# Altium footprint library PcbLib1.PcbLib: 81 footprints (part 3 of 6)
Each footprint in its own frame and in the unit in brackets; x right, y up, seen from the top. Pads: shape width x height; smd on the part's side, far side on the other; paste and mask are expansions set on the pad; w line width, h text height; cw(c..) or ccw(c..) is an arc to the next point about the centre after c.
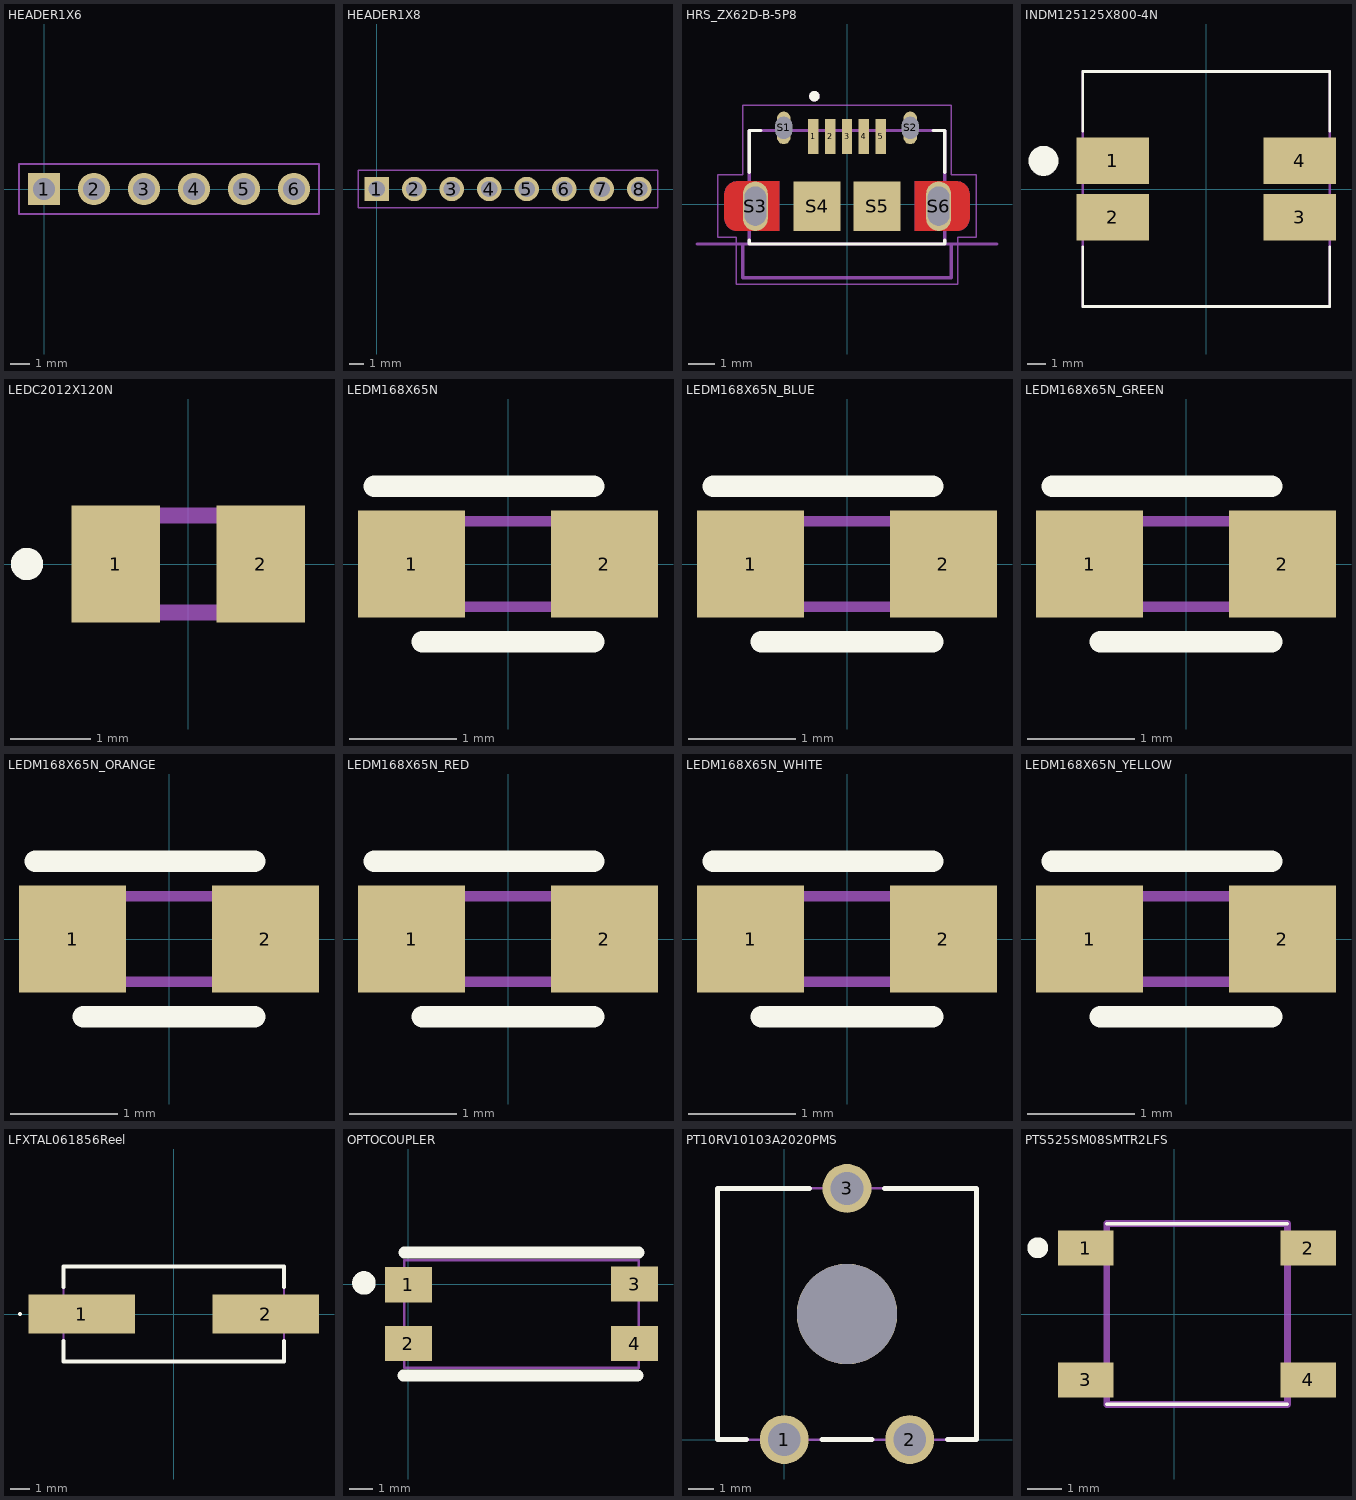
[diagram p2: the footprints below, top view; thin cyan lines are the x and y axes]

## HEADER1X6 [mm]
pads (6):
  rect 1.65x1.65 hole 1.1: 1(0,0)
  round 1.65 hole 1.1: 2(2.54,0) 3(5.08,0) 4(7.62,0) 5(10.16,0) 6(12.7,0)
Mechanical 13:
  lines w0.1: -1.27,-1.27 -1.27,1.27 13.97,1.27 13.97,-1.27 -1.27,-1.27
3D body "0901471106.stp": height 8.7, standoff -3.1, extent -1.195,-1.22 13.895,1.22

## HEADER1X8 [mm]
pads (8):
  rect 1.65x1.65 hole 1.1: 1(0,0)
  round 1.65 hole 1.1: 2(2.54,0) 3(5.08,0) 4(7.62,0) 5(10.16,0) 6(12.7,0) 7(15.24,0) 8(17.78,0)
Mechanical 13:
  lines w0.1: -1.27,-1.27 19.05,-1.27 19.05,1.27 -1.27,1.27 -1.27,-1.27
3D body "m20-9990246_asm.stp": height 8.7, standoff -2.98, extent 13.97,-1.27 19.05,1.27
3D body "m20-9990246_asm.stp": height 8.7, standoff -2.98, extent 8.89,-1.27 13.97,1.27
3D body "m20-9990246_asm.stp": height 8.7, standoff -2.98, extent 3.81,-1.27 8.89,1.27
3D body "m20-9990246_asm.stp": height 8.7, standoff -2.98, extent -1.27,-1.27 3.81,1.27

## HRS_ZX62D-B-5P8 [mm]
pads (11):
  rect 0.4x1.35 smd mask+0.1: 1(-1.3,2.6) 2(-0.65,2.6) 3(0,2.6) 4(0.65,2.6) 5(1.3,2.6)
  oval 0.525x1.25 hole 0.65 slot 0.85 at 90 deg mask+0.1: S1(-2.425,2.925) S2(2.425,2.925)
  oval 0.95x1.9 hole 0.825 slot 1.5 at 90 deg mask+0.1: S3(-3.512,-0.075) S6(3.512,-0.075)
  rect 1.8x1.9 smd mask+0.1: S4(-1.15,-0.075) S5(1.15,-0.075)
Top Layer:
  region: -2.6,-0.075 -3.1,-0.075 -3.1,0.375 -3.1,0.391 -3.102,0.406 -3.104,0.422 -3.107,0.437 -3.11,0.453 -3.115,0.468 -3.12,0.483 -3.126,0.497 -3.133,0.511 -3.14,0.525 -3.148,0.538 -3.157,0.551 -3.167,0.564 -3.177,0.576 -3.188,0.587 -3.199,0.598 -3.211,0.608 -3.224,0.618 -3.237,0.627 -3.25,0.635 -3.264,0.642 -3.278,0.649 -3.292,0.655 -3.307,0.66 -3.322,0.665 -3.338,0.668 -3.353,0.671 -3.369,0.673 -3.384,0.675 -3.641,0.675 -3.656,0.673 -3.672,0.671 -3.687,0.668 -3.703,0.665 -3.718,0.66 -3.733,0.655 -3.747,0.649 -3.761,0.642 -3.775,0.635 -3.788,0.627 -3.801,0.618 -3.814,0.608 -3.826,0.598 -3.837,0.587 -3.848,0.576 -3.858,0.564 -3.868,0.551 -3.877,0.538 -3.885,0.525 -3.892,0.511 -3.899,0.497 -3.905,0.483 -3.91,0.468 -3.915,0.453 -3.918,0.437 -3.921,0.422 -3.923,0.406 -3.925,0.391 -3.925,0.375 -3.925,-0.075 -4.7,-0.075 -4.7,0.375 -4.699,0.401 -4.697,0.427 -4.694,0.453 -4.689,0.479 -4.683,0.504 -4.676,0.53 -4.667,0.554 -4.657,0.578 -4.646,0.602 -4.633,0.625 -4.619,0.647 -4.605,0.669 -4.589,0.69 -4.572,0.71 -4.554,0.729 -4.535,0.747 -4.515,0.764 -4.494,0.78 -4.472,0.794 -4.45,0.808 -4.427,0.821 -4.403,0.832 -4.379,0.842 -4.355,0.851 -4.329,0.858 -4.304,0.864 -4.278,0.869 -4.252,0.872 -4.226,0.874 -4.2,0.875 -2.6,0.875
  region: 4.7,-0.525 4.699,-0.551 4.697,-0.577 4.694,-0.603 4.689,-0.629 4.683,-0.654 4.676,-0.68 4.667,-0.704 4.657,-0.728 4.646,-0.752 4.633,-0.775 4.619,-0.797 4.605,-0.819 4.589,-0.84 4.572,-0.86 4.554,-0.879 4.535,-0.897 4.515,-0.914 4.494,-0.93 4.472,-0.944 4.45,-0.958 4.427,-0.971 4.403,-0.982 4.379,-0.992 4.355,-1.001 4.329,-1.008 4.304,-1.014 4.278,-1.019 4.252,-1.022 4.226,-1.024 4.2,-1.025 2.6,-1.025 2.6,-0.075 3.1,-0.075 3.1,-0.525 3.1,-0.541 3.102,-0.556 3.104,-0.572 3.107,-0.587 3.11,-0.603 3.115,-0.618 3.12,-0.633 3.126,-0.647 3.133,-0.661 3.14,-0.675 3.148,-0.688 3.157,-0.701 3.167,-0.714 3.177,-0.726 3.188,-0.737 3.199,-0.748 3.211,-0.758 3.224,-0.768 3.237,-0.777 3.25,-0.785 3.264,-0.792 3.278,-0.799 3.292,-0.805 3.307,-0.81 3.322,-0.815 3.338,-0.818 3.353,-0.821 3.369,-0.823 3.384,-0.825 3.641,-0.825 3.656,-0.823 3.672,-0.821 3.687,-0.818 3.703,-0.815 3.718,-0.81 3.733,-0.805 3.747,-0.799 3.761,-0.792 3.775,-0.785 3.788,-0.777 3.801,-0.768 3.814,-0.758 3.826,-0.748 3.837,-0.737 3.848,-0.726 3.858,-0.714 3.868,-0.701 3.877,-0.688 3.885,-0.675 3.892,-0.661 3.899,-0.647 3.905,-0.633 3.91,-0.618 3.915,-0.603 3.918,-0.587 3.921,-0.572 3.923,-0.556 3.925,-0.541 3.925,-0.525 3.925,-0.075 4.7,-0.075
  region: -2.6,-1.025 -4.2,-1.025 -4.226,-1.024 -4.252,-1.022 -4.278,-1.019 -4.304,-1.014 -4.329,-1.008 -4.355,-1.001 -4.379,-0.992 -4.403,-0.982 -4.427,-0.971 -4.45,-0.958 -4.472,-0.944 -4.494,-0.93 -4.515,-0.914 -4.535,-0.897 -4.554,-0.879 -4.572,-0.86 -4.589,-0.84 -4.605,-0.819 -4.619,-0.797 -4.633,-0.775 -4.646,-0.752 -4.657,-0.728 -4.667,-0.704 -4.676,-0.68 -4.683,-0.654 -4.689,-0.629 -4.694,-0.603 -4.697,-0.577 -4.699,-0.551 -4.7,-0.525 -4.7,-0.075 -3.925,-0.075 -3.925,-0.55 -3.925,-0.564 -3.923,-0.579 -3.922,-0.593 -3.919,-0.607 -3.916,-0.621 -3.912,-0.635 -3.907,-0.649 -3.901,-0.662 -3.895,-0.675 -3.888,-0.688 -3.881,-0.7 -3.872,-0.712 -3.864,-0.723 -3.854,-0.734 -3.844,-0.744 -3.834,-0.754 -3.823,-0.764 -3.812,-0.772 -3.8,-0.781 -3.787,-0.788 -3.775,-0.795 -3.762,-0.801 -3.749,-0.807 -3.735,-0.812 -3.721,-0.816 -3.707,-0.819 -3.693,-0.822 -3.679,-0.823 -3.664,-0.825 -3.384,-0.825 -3.369,-0.823 -3.353,-0.821 -3.338,-0.818 -3.322,-0.815 -3.307,-0.81 -3.292,-0.805 -3.278,-0.799 -3.264,-0.792 -3.25,-0.785 -3.237,-0.777 -3.224,-0.768 -3.211,-0.758 -3.199,-0.748 -3.188,-0.737 -3.177,-0.726 -3.167,-0.714 -3.157,-0.701 -3.148,-0.688 -3.14,-0.675 -3.133,-0.661 -3.126,-0.647 -3.12,-0.633 -3.115,-0.618 -3.11,-0.603 -3.107,-0.587 -3.104,-0.572 -3.102,-0.556 -3.1,-0.541 -3.1,-0.525 -3.1,-0.075 -2.6,-0.075
  region: 4.226,0.874 4.252,0.872 4.278,0.869 4.304,0.864 4.329,0.858 4.355,0.851 4.379,0.842 4.403,0.832 4.427,0.821 4.45,0.808 4.472,0.794 4.494,0.78 4.515,0.764 4.535,0.747 4.554,0.729 4.572,0.71 4.589,0.69 4.605,0.669 4.619,0.647 4.633,0.625 4.646,0.602 4.657,0.578 4.667,0.554 4.676,0.53 4.683,0.504 4.689,0.479 4.694,0.453 4.697,0.427 4.699,0.401 4.7,0.375 4.7,-0.075 3.925,-0.075 3.925,0.4 3.925,0.414 3.923,0.429 3.922,0.443 3.919,0.457 3.916,0.471 3.912,0.485 3.907,0.499 3.901,0.512 3.895,0.525 3.888,0.538 3.881,0.55 3.872,0.562 3.864,0.573 3.854,0.584 3.844,0.594 3.834,0.604 3.823,0.614 3.812,0.622 3.8,0.631 3.787,0.638 3.775,0.645 3.762,0.651 3.749,0.657 3.735,0.662 3.721,0.666 3.707,0.669 3.693,0.672 3.679,0.673 3.664,0.675 3.384,0.675 3.369,0.673 3.353,0.671 3.338,0.668 3.322,0.665 3.307,0.66 3.292,0.655 3.278,0.649 3.264,0.642 3.25,0.635 3.237,0.627 3.224,0.618 3.211,0.608 3.199,0.598 3.188,0.587 3.177,0.576 3.167,0.564 3.157,0.551 3.148,0.538 3.14,0.525 3.133,0.511 3.126,0.497 3.12,0.483 3.115,0.468 3.11,0.453 3.107,0.437 3.104,0.422 3.102,0.406 3.1,0.391 3.1,0.375 3.1,-0.075 2.6,-0.075 2.6,0.875 4.2,0.875
Bottom Layer:
  region: -2.6,-0.075 -3.1,-0.075 -3.1,0.375 -3.1,0.391 -3.102,0.406 -3.104,0.422 -3.107,0.437 -3.11,0.453 -3.115,0.468 -3.12,0.483 -3.126,0.497 -3.133,0.511 -3.14,0.525 -3.148,0.538 -3.157,0.551 -3.167,0.564 -3.177,0.576 -3.188,0.587 -3.199,0.598 -3.211,0.608 -3.224,0.618 -3.237,0.627 -3.25,0.635 -3.264,0.642 -3.278,0.649 -3.292,0.655 -3.307,0.66 -3.322,0.665 -3.338,0.668 -3.353,0.671 -3.369,0.673 -3.384,0.675 -3.641,0.675 -3.656,0.673 -3.672,0.671 -3.687,0.668 -3.703,0.665 -3.718,0.66 -3.733,0.655 -3.747,0.649 -3.761,0.642 -3.775,0.635 -3.788,0.627 -3.801,0.618 -3.814,0.608 -3.826,0.598 -3.837,0.587 -3.848,0.576 -3.858,0.564 -3.868,0.551 -3.877,0.538 -3.885,0.525 -3.892,0.511 -3.899,0.497 -3.905,0.483 -3.91,0.468 -3.915,0.453 -3.918,0.437 -3.921,0.422 -3.923,0.406 -3.925,0.391 -3.925,0.375 -3.925,-0.075 -4.7,-0.075 -4.7,0.375 -4.699,0.401 -4.697,0.427 -4.694,0.453 -4.689,0.479 -4.683,0.504 -4.676,0.53 -4.667,0.554 -4.657,0.578 -4.646,0.602 -4.633,0.625 -4.619,0.647 -4.605,0.669 -4.589,0.69 -4.572,0.71 -4.554,0.729 -4.535,0.747 -4.515,0.764 -4.494,0.78 -4.472,0.794 -4.45,0.808 -4.427,0.821 -4.403,0.832 -4.379,0.842 -4.355,0.851 -4.329,0.858 -4.304,0.864 -4.278,0.869 -4.252,0.872 -4.226,0.874 -4.2,0.875 -2.6,0.875
  region: 4.7,-0.525 4.699,-0.551 4.697,-0.577 4.694,-0.603 4.689,-0.629 4.683,-0.654 4.676,-0.68 4.667,-0.704 4.657,-0.728 4.646,-0.752 4.633,-0.775 4.619,-0.797 4.605,-0.819 4.589,-0.84 4.572,-0.86 4.554,-0.879 4.535,-0.897 4.515,-0.914 4.494,-0.93 4.472,-0.944 4.45,-0.958 4.427,-0.971 4.403,-0.982 4.379,-0.992 4.355,-1.001 4.329,-1.008 4.304,-1.014 4.278,-1.019 4.252,-1.022 4.226,-1.024 4.2,-1.025 2.6,-1.025 2.6,-0.075 3.1,-0.075 3.1,-0.525 3.1,-0.541 3.102,-0.556 3.104,-0.572 3.107,-0.587 3.11,-0.603 3.115,-0.618 3.12,-0.633 3.126,-0.647 3.133,-0.661 3.14,-0.675 3.148,-0.688 3.157,-0.701 3.167,-0.714 3.177,-0.726 3.188,-0.737 3.199,-0.748 3.211,-0.758 3.224,-0.768 3.237,-0.777 3.25,-0.785 3.264,-0.792 3.278,-0.799 3.292,-0.805 3.307,-0.81 3.322,-0.815 3.338,-0.818 3.353,-0.821 3.369,-0.823 3.384,-0.825 3.641,-0.825 3.656,-0.823 3.672,-0.821 3.687,-0.818 3.703,-0.815 3.718,-0.81 3.733,-0.805 3.747,-0.799 3.761,-0.792 3.775,-0.785 3.788,-0.777 3.801,-0.768 3.814,-0.758 3.826,-0.748 3.837,-0.737 3.848,-0.726 3.858,-0.714 3.868,-0.701 3.877,-0.688 3.885,-0.675 3.892,-0.661 3.899,-0.647 3.905,-0.633 3.91,-0.618 3.915,-0.603 3.918,-0.587 3.921,-0.572 3.923,-0.556 3.925,-0.541 3.925,-0.525 3.925,-0.075 4.7,-0.075
  region: -2.6,-1.025 -4.2,-1.025 -4.226,-1.024 -4.252,-1.022 -4.278,-1.019 -4.304,-1.014 -4.329,-1.008 -4.355,-1.001 -4.379,-0.992 -4.403,-0.982 -4.427,-0.971 -4.45,-0.958 -4.472,-0.944 -4.494,-0.93 -4.515,-0.914 -4.535,-0.897 -4.554,-0.879 -4.572,-0.86 -4.589,-0.84 -4.605,-0.819 -4.619,-0.797 -4.633,-0.775 -4.646,-0.752 -4.657,-0.728 -4.667,-0.704 -4.676,-0.68 -4.683,-0.654 -4.689,-0.629 -4.694,-0.603 -4.697,-0.577 -4.699,-0.551 -4.7,-0.525 -4.7,-0.075 -3.925,-0.075 -3.925,-0.55 -3.925,-0.564 -3.923,-0.579 -3.922,-0.593 -3.919,-0.607 -3.916,-0.621 -3.912,-0.635 -3.907,-0.649 -3.901,-0.662 -3.895,-0.675 -3.888,-0.688 -3.881,-0.7 -3.872,-0.712 -3.864,-0.723 -3.854,-0.734 -3.844,-0.744 -3.834,-0.754 -3.823,-0.764 -3.812,-0.772 -3.8,-0.781 -3.787,-0.788 -3.775,-0.795 -3.762,-0.801 -3.749,-0.807 -3.735,-0.812 -3.721,-0.816 -3.707,-0.819 -3.693,-0.822 -3.679,-0.823 -3.664,-0.825 -3.384,-0.825 -3.369,-0.823 -3.353,-0.821 -3.338,-0.818 -3.322,-0.815 -3.307,-0.81 -3.292,-0.805 -3.278,-0.799 -3.264,-0.792 -3.25,-0.785 -3.237,-0.777 -3.224,-0.768 -3.211,-0.758 -3.199,-0.748 -3.188,-0.737 -3.177,-0.726 -3.167,-0.714 -3.157,-0.701 -3.148,-0.688 -3.14,-0.675 -3.133,-0.661 -3.126,-0.647 -3.12,-0.633 -3.115,-0.618 -3.11,-0.603 -3.107,-0.587 -3.104,-0.572 -3.102,-0.556 -3.1,-0.541 -3.1,-0.525 -3.1,-0.075 -2.6,-0.075
  region: 4.226,0.874 4.252,0.872 4.278,0.869 4.304,0.864 4.329,0.858 4.355,0.851 4.379,0.842 4.403,0.832 4.427,0.821 4.45,0.808 4.472,0.794 4.494,0.78 4.515,0.764 4.535,0.747 4.554,0.729 4.572,0.71 4.589,0.69 4.605,0.669 4.619,0.647 4.633,0.625 4.646,0.602 4.657,0.578 4.667,0.554 4.676,0.53 4.683,0.504 4.689,0.479 4.694,0.453 4.697,0.427 4.699,0.401 4.7,0.375 4.7,-0.075 3.925,-0.075 3.925,0.4 3.925,0.414 3.923,0.429 3.922,0.443 3.919,0.457 3.916,0.471 3.912,0.485 3.907,0.499 3.901,0.512 3.895,0.525 3.888,0.538 3.881,0.55 3.872,0.562 3.864,0.573 3.854,0.584 3.844,0.594 3.834,0.604 3.823,0.614 3.812,0.622 3.8,0.631 3.787,0.638 3.775,0.645 3.762,0.651 3.749,0.657 3.735,0.662 3.721,0.666 3.707,0.669 3.693,0.672 3.679,0.673 3.664,0.675 3.384,0.675 3.369,0.673 3.353,0.671 3.338,0.668 3.322,0.665 3.307,0.66 3.292,0.655 3.278,0.649 3.264,0.642 3.25,0.635 3.237,0.627 3.224,0.618 3.211,0.608 3.199,0.598 3.188,0.587 3.177,0.576 3.167,0.564 3.157,0.551 3.148,0.538 3.14,0.525 3.133,0.511 3.126,0.497 3.12,0.483 3.115,0.468 3.11,0.453 3.107,0.437 3.104,0.422 3.102,0.406 3.1,0.391 3.1,0.375 3.1,-0.075 2.6,-0.075 2.6,0.875 4.2,0.875
Top Overlay:
  circle w0.2: c-1.25,4.14 r0.1
  lines w0.127: -3.75,-1.375 -3.75,-1.525 3.75,-1.525 3.75,-1.375 ; -3.75,1.225 -3.75,2.825 -3.3,2.825 ; 3.3,2.825 3.75,2.825 3.75,1.225
Top Paste:
  drawing of 8 lines, arcs and shapes, not listed
Bottom Paste:
  drawing of 8 lines, arcs and shapes, not listed
Top Solder:
  region: -2.5,-1.126 -4.801,-1.126 -4.801,0.975 -2.5,0.975
  region: 4.8,-1.128 2.502,-1.128 2.502,0.975 4.8,0.975
Bottom Solder:
  region: -2.5,0.875 -2.6,0.875 -2.6,-1.025 -2.5,-1.025 -2.5,-1.126 -4.801,-1.126 -4.801,0.975 -2.5,0.975
  region: 4.8,-1.128 2.502,-1.128 2.502,-1.025 2.6,-1.025 2.6,0.875 2.502,0.875 2.502,0.975 4.8,0.975
Mechanical 13:
  circle w0.2: c-1.25,4.14 r0.1
  lines w0.127: -5.75,-1.525 -3.75,-1.525 ; -4,-1.525 -4,-2.825 4,-2.825 4,-1.525 ; 5.75,-1.525 3.75,-1.525 ; -3.75,-1.525 -3.75,2.825 3.75,2.825 3.75,-1.525 ; -3.75,-1.525 3.75,-1.525
Mechanical 15:
  lines w0.05: -4.95,-1.275 -4.95,1.125 -4,1.125 -4,3.8 4,3.8 4,1.125 4.95,1.125 4.95,-1.275 4.25,-1.275 4.25,-3.075 -4.25,-3.075 -4.25,-1.275 -4.95,-1.275
3D body "step_temp.STEP": height 1.48, standoff -2.02, extent -4.047,-2.95 4.047,2.85

## INDM125125X800-4N [mil]
pads (4):
  rect 152x98 smd: 1(-196,59) 2(-196,-59) 3(196,-59) 4(196,59)
Top Overlay:
  lines w6: -258.86,-121 -258.86,-246 258.86,-246 258.86,-121 ; -258.86,121 -258.86,246 258.86,246 258.86,121
  lines w31.5: -356.75,59 cw(c-341,59) -325.25,59 cw(c-341,59) -356.75,59
Mechanical 13:
  lines w6: -341,56 cw(c-341,59) -341,62 cw(c-341,59) -341,56 ; -258.86,-246 -258.86,246.06 258.8,246.06 258.8,-246 -258.86,-246
3D body "DRQ127.step": height 315, standoff 0, extent -258.23,-245.98 258.23,245.98

## LEDC2012X120N [mm]
pads (2):
  rect 1.1x1.45 smd: 1(-0.9,0) 2(0.9,0)
Top Overlay:
  circle w0.2: c-2,0 r0.1
Mechanical 13:
  region: -0.5,-0.633 -1.055,-0.633 -1.055,0.6 -0.5,0.6
  region: 1,-0.631 0.526,-0.631 0.526,0.6 1,0.6
  lines w0.2: -1,-0.6 1,-0.6 1,0.6 -1,0.6 -1,-0.6

## LEDM168X65N [mm]
pads (2):
  rect 1x1 smd: 1(-0.9,0) 2(0.9,0)
Top Overlay:
  lines w0.2: -1.25,0.725 0.8,0.725 ; -0.8,-0.725 0.8,-0.725
Mechanical 13:
  lines w0.1: -0.8,0.05 -0.45,0.4 ; -0.8,-0.4 0.8,-0.4 0.8,0.4 -0.8,0.4 -0.8,-0.4
3D body "User Library-LED_0603_B.STEP": height 0.6, standoff 0, extent -0.8,-0.4 0.8,0.4

## LEDM168X65N_BLUE [mm]
pads (2):
  rect 1x1 smd: 1(-0.9,0) 2(0.9,0)
Top Overlay:
  lines w0.2: -1.25,0.725 0.8,0.725 ; -0.8,-0.725 0.8,-0.725
Mechanical 13:
  lines w0.1: -0.8,0.05 -0.45,0.4 ; -0.8,-0.4 0.8,-0.4 0.8,0.4 -0.8,0.4 -0.8,-0.4
3D body "User Library-LED_0603_B.STEP": height 0.6, standoff 0, extent -0.8,-0.4 0.8,0.4

## LEDM168X65N_GREEN [mm]
pads (2):
  rect 1x1 smd: 1(-0.9,0) 2(0.9,0)
Top Overlay:
  lines w0.2: -1.25,0.725 0.8,0.725 ; -0.8,-0.725 0.8,-0.725
Mechanical 13:
  lines w0.1: -0.8,0.05 -0.45,0.4 ; -0.8,-0.4 -0.8,0.4 0.8,0.4 0.8,-0.4 -0.8,-0.4
3D body "User Library-LED_0603_G.STEP": height 0.6, standoff 0, extent -0.8,-0.4 0.8,0.4

## LEDM168X65N_ORANGE [mm]
pads (2):
  rect 1x1 smd: 1(-0.9,0) 2(0.9,0)
Top Overlay:
  lines w0.2: -1.25,0.725 0.8,0.725 ; -0.8,-0.725 0.8,-0.725
Mechanical 13:
  lines w0.1: -0.8,0.05 -0.45,0.4 ; -0.8,-0.4 0.8,-0.4 0.8,0.4 -0.8,0.4 -0.8,-0.4
3D body "User Library-0603 LED_ora.STEP": height 0.7, standoff 0, extent -0.8,-0.4 0.8,0.4

## LEDM168X65N_RED [mm]
pads (2):
  rect 1x1 smd: 1(-0.9,0) 2(0.9,0)
Top Overlay:
  lines w0.2: -1.25,0.725 0.8,0.725 ; -0.8,-0.725 0.8,-0.725
Mechanical 13:
  lines w0.1: -0.8,0.05 -0.45,0.4 ; -0.8,-0.4 0.8,-0.4 0.8,0.4 -0.8,0.4 -0.8,-0.4
3D body "User Library-LED_0603_R.STEP": height 0.6, standoff 0, extent -0.8,-0.4 0.8,0.4

## LEDM168X65N_WHITE [mm]
pads (2):
  rect 1x1 smd: 1(-0.9,0) 2(0.9,0)
Top Overlay:
  lines w0.2: -1.25,0.725 0.8,0.725 ; -0.8,-0.725 0.8,-0.725
Mechanical 13:
  lines w0.1: -0.8,0.05 -0.45,0.4 ; -0.8,-0.4 0.8,-0.4 0.8,0.4 -0.8,0.4 -0.8,-0.4
3D body "User Library-LED_0603_WS.STEP": height 0.6, standoff 0, extent -0.8,-0.4 0.8,0.4

## LEDM168X65N_YELLOW [mm]
pads (2):
  rect 1x1 smd: 1(-0.9,0) 2(0.9,0)
Top Overlay:
  lines w0.2: -1.25,0.725 0.8,0.725 ; -0.8,-0.725 0.8,-0.725
Mechanical 13:
  lines w0.1: -0.8,0.05 -0.45,0.4 ; -0.8,-0.4 -0.8,0.4 0.8,0.4 0.8,-0.4 -0.8,-0.4
3D body "User Library-LED_0603_Y.STEP": height 0.6, standoff 0, extent -0.8,-0.4 0.8,0.4

## LFXTAL061856Reel [mm]
pads (2):
  rect 5.5x2 smd: 1(-4.75,0) 2(4.75,0)
Top Overlay:
  lines w0.1: -8,0 cw(c-7.95,0) -7.9,0 cw(c-7.95,0) -8,0
  lines w0.2: -5.7,-1.4 -5.7,-2.45 5.7,-2.45 5.7,-1.4 ; -5.7,1.4 -5.7,2.45 5.7,2.45 5.7,1.4
Mechanical 13:
  lines w0.1: -5.7,-2.45 -5.7,2.45 5.7,2.45 5.7,-2.45 -5.7,-2.45
3D body "LFXTAL061856Reel.stp": height 4.4, standoff 0, extent -7.3,-2.45 7.3,2.45

## OPTOCOUPLER [mm]
pads (4):
  rect 2x1.5 smd: 1(0,-0.025) 2(0,-2.54) 3(9.65,0) 4(9.65,-2.54)
Top Overlay:
  circle w0.5: c-1.9,0.05 r0.251
  lines w0.5: -0.225,-3.9 9.775,-3.9 ; -0.175,1.35 9.825,1.35
Mechanical 13:
  lines w0.1: -0.175,-3.575 9.825,-3.575 9.825,1.025 -0.175,1.025 -0.175,-3.575
3D body "PC817X2CSP9F.STEP": height 4, standoff 0, extent -0.175,-3.565 9.825,1.015

## PT10RV10103A2020PMS [mm]
pads (4):
  round 1.95 hole 1.3: 1(0,0) 2(5,0) 3(2.5,10)
  round 4 hole 4 unplated: ""(2.5,5)
Top Overlay:
  lines w0.2: -1.5,0 -2.65,0 -2.65,10 1,10 ; 1.5,0 3.5,0 ; 4,10 7.65,10 7.65,0 6.5,0
Mechanical 13:
  lines w0.1: -2.65,0 -2.65,10 7.65,10 7.65,0 -2.65,0
3D body "3319P-1-504.STEP": height 6.86, standoff -4, extent -1.6,-1.025 7.4,10.774

## PTS525SM08SMTR2LFS [mm]
pads (4):
  rect 1.6x1 smd: 1(-2.55,1.9) 2(3.85,1.9) 3(-2.55,-1.9) 4(3.85,-1.9)
Top Overlay:
  lines w0.1: -1.95,-2.6 3.25,-2.6 ; -1.95,2.6 3.25,2.6
  lines w0.5: -3.987,1.905 cw(c-3.937,1.905) -3.887,1.905 cw(c-3.937,1.905) -3.987,1.905
Mechanical 13:
  lines w0.2: -1.95,-2.6 -1.95,2.6 3.25,2.6 3.25,-2.6 -1.95,-2.6
3D body "TL3305AF160QG--3DModel-STEP-520916.STEP": height 3.7, standoff -0.1, extent -3.115,-2.25 4.385,2.25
